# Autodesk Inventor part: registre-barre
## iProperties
Author: chr
Created: 2001-06
Part Number: registre-barre
Material: Par défaut
Document SubType Name: Modélisation
Designer: chr
Control State: 0
Master: False
Checked Out: False
PropertySet Name: Design Tracking Control
Shininess: 21.0
PropertySet Name: _Private Model Information
Length Units: 11269
Angle Units: 11286
Time Units: 11279
Mass Units: 11290
Length Display Precision: 3
Angle Display Precision: 2
Compacted: False
Density: 0.0
Volumn: 0.0
Area: 0.0
PropertySet Name: Model Information
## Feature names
1. Extrusion1
2. Extrusion2
